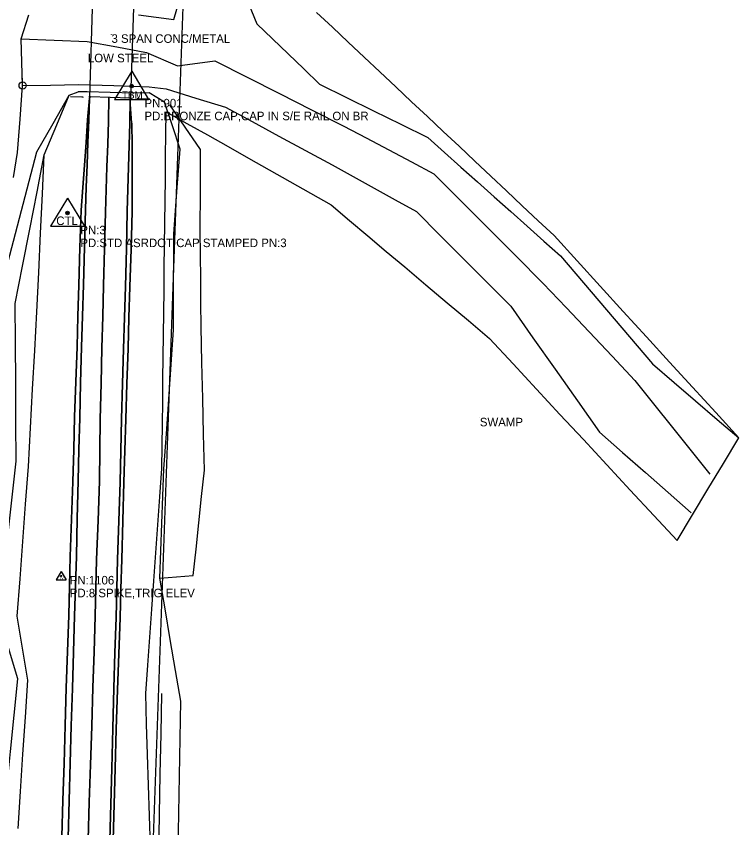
# Model space of a CAD drawing. Extents: x 1445297 to 1476720, y 2042269 to 2057889.
# Drawn here: x 1446040.2 to 1446463.1, y 2043652.1 to 2044126.9 of the extents above; entities that cross this region are included whole.
import ezdxf

# ---------------------------------------------------------------- set-up
doc = ezdxf.new("R2010")
doc.units = 0
for name, color, linetype in [('S_BRIDGE', 7, 'Continuous'), ('S_DITCHLINE', 7, 'Continuous'), ('S_EDGE_PAVEMENT', 7, 'Continuous'), ('S_MSC_PT_SYM', 7, 'Continuous'), ('S_PAVEMENT_CROWN', 7, 'Continuous'), ('S_PRIMARY_CTL', 7, 'Continuous'), ('S_PRIMARY_CTL_ANNOT', 7, 'Continuous'), ('S_SECONDARY_CTL', 7, 'Continuous'), ('S_SECONDARY_CTL_ANNOT', 7, 'Continuous'), ('S_SHOULDER', 7, 'Continuous'), ('S_STR_PT_SYM', 7, 'Continuous'), ('S_STREAM', 7, 'Continuous'), ('S_SURVEY_TEXT_ANNOT', 7, 'Continuous'), ('S_TREE', 7, 'Continuous'), ('S_UNDERGROUND_CABLE', 7, 'Continuous'), ('S_UTILITY_POLE', 7, 'Continuous'), ('S_WALL', 7, 'Continuous')]:
    doc.layers.add(name, color=color, linetype=linetype)

msp = doc.modelspace()

# ---------------------------------------------------------------- linework, layer by layer
at = {"layer": 'S_BRIDGE'}
for p, q in [((1446083.17, 2044079.68), (1446085.63, 2044154.69)), ((1446109.56, 2044154.24), (1446107.11, 2044078.9)), ((1446107.11, 2044078.9), (1446083.17, 2044079.68))]:
    msp.add_line(p, q, dxfattribs=at)
at = {"layer": 'S_DITCHLINE'}
for points in [[(1446111.81, 2044127.68), (1446132.33, 2044125.05), (1446137.31, 2044142.04)], [(1446174.36, 2044138.84), (1446180.96, 2044122.53), (1446190.14, 2044113.71), (1446199.32, 2044104.89), (1446208.5, 2044096.07), (1446217.68, 2044087.25), (1446233.53, 2044079.42), (1446249.37, 2044071.6), (1446265.21, 2044063.78), (1446281.05, 2044055.96), (1446290.76, 2044047.3), (1446300.47, 2044038.65), (1446310.17, 2044030), (1446319.88, 2044021.34), (1446329.59, 2044012.69), (1446339.29, 2044004.04), (1446349, 2043995.38), (1446358.71, 2043986.73), (1446372.18, 2043970.94), (1446385.64, 2043955.15), (1446399.11, 2043939.36), (1446412.57, 2043923.57), (1446425.2, 2043912.73), (1446437.84, 2043901.89), (1446450.47, 2043891.05), (1446463.1, 2043880.22)], [(1446038.65, 2044032.61), (1446041.01, 2044047.21), (1446042.47, 2044066.79), (1446043.93, 2044086.37), (1446043.53, 2044100.06), (1446043.13, 2044113.76), (1446047.64, 2044127.65)], [(1446043.13, 2044113.76), (1446062.46, 2044112.97), (1446081.78, 2044112.19), (1446099.08, 2044108.95), (1446116.39, 2044105.72), (1446134.56, 2044098), (1446156.52, 2044100.9), (1446175.36, 2044091.35), (1446194.2, 2044081.8), (1446213.05, 2044072.25), (1446231.89, 2044062.7), (1446245.08, 2044055.7), (1446258.27, 2044048.7), (1446271.47, 2044041.7), (1446284.66, 2044034.7), (1446300.63, 2044018.69), (1446316.61, 2044002.68), (1446332.59, 2043986.67), (1446348.57, 2043970.66), (1446362.01, 2043956.44), (1446375.45, 2043942.23), (1446388.9, 2043928.01), (1446402.34, 2043913.8), (1446413.28, 2043900.08), (1446424.21, 2043886.36), (1446435.14, 2043872.65), (1446446.08, 2043858.93)], [(1446043.93, 2044086.37), (1446060.25, 2044086.69), (1446076.57, 2044087.02), (1446097.32, 2044086.35), (1446118.08, 2044085.69), (1446127.94, 2044084.37), (1446145.34, 2044079.07), (1446162.74, 2044073.77), (1446178.33, 2044065.3), (1446193.92, 2044056.84), (1446209.51, 2044048.37), (1446225.1, 2044039.91), (1446237.42, 2044033.11), (1446249.74, 2044026.3), (1446262.05, 2044019.5), (1446274.37, 2044012.7), (1446288.18, 2043998.86), (1446302, 2043985.01), (1446315.81, 2043971.17), (1446329.62, 2043957.33), (1446342.63, 2043938.87), (1446355.64, 2043920.42), (1446368.65, 2043901.96), (1446381.66, 2043883.51), (1446395.05, 2043871.75), (1446408.44, 2043859.99), (1446421.82, 2043848.22), (1446435.21, 2043836.46)], [(1446041.28, 2043651.77), (1446042.71, 2043673.46), (1446044.14, 2043695.15), (1446045.57, 2043716.83), (1446047, 2043738.52), (1446043.87, 2043757.24), (1446040.73, 2043775.97), (1446042.39, 2043797.83), (1446044.04, 2043819.69), (1446045.69, 2043841.55), (1446047.35, 2043863.41), (1446048.57, 2043886.07), (1446049.79, 2043908.72), (1446051.01, 2043931.37), (1446052.23, 2043954.03), (1446053.33, 2043977), (1446054.42, 2043999.98), (1446055.51, 2044022.95), (1446056.6, 2044045.93), (1446063.91, 2044063.32), (1446071.21, 2044080.71)], [(1446134.89, 2043638.83), (1446135.28, 2043660.7), (1446135.66, 2043682.57), (1446136.05, 2043704.44), (1446136.44, 2043726.3), (1446133.38, 2043744.25), (1446130.32, 2043762.2), (1446127.26, 2043780.15), (1446124.2, 2043798.09), (1446143.79, 2043799.66), (1446145.41, 2043815.11), (1446147.04, 2043830.55), (1446148.67, 2043846), (1446150.3, 2043861.45), (1446149.83, 2043882.4), (1446149.36, 2043903.35), (1446148.89, 2043924.3), (1446148.42, 2043945.25), (1446148.29, 2043959.26), (1446148.16, 2043973.27), (1446148.02, 2043987.27), (1446147.89, 2044001.28), (1446147.95, 2044025.12), (1446148.02, 2044048.97), (1446139.09, 2044062.06), (1446130.17, 2044075.16)], [(1446134.89, 2043638.83), (1446135.28, 2043660.7), (1446135.66, 2043682.57), (1446136.05, 2043704.44), (1446136.44, 2043726.3), (1446133.38, 2043744.25), (1446130.32, 2043762.2), (1446127.26, 2043780.15), (1446124.2, 2043798.09), (1446143.79, 2043799.66), (1446145.41, 2043815.11), (1446147.04, 2043830.55), (1446148.67, 2043846), (1446150.3, 2043861.45), (1446149.83, 2043882.4), (1446149.36, 2043903.35), (1446148.89, 2043924.3), (1446148.42, 2043945.25), (1446148.29, 2043959.26), (1446148.16, 2043973.27), (1446148.02, 2043987.27), (1446147.89, 2044001.28), (1446147.95, 2044025.12), (1446148.02, 2044048.97), (1446139.09, 2044062.06), (1446130.17, 2044075.16)], [(1446033.44, 2043639.99), (1446032.52, 2043654.08), (1446034.68, 2043675.4), (1446036.84, 2043696.72), (1446039, 2043718.04), (1446041.15, 2043739.36), (1446035.65, 2043757.41), (1446030.16, 2043775.47), (1446032.65, 2043798.24), (1446035.14, 2043821.02), (1446037.63, 2043843.79), (1446040.13, 2043866.56), (1446040, 2043889.64), (1446039.87, 2043912.72), (1446039.74, 2043935.8), (1446039.61, 2043958.89), (1446043.86, 2043980.65), (1446048.11, 2044002.41), (1446052.36, 2044024.17), (1446056.6, 2044045.93)], [(1446123.61, 2043636.2), (1446124.06, 2043659.83), (1446124.51, 2043683.45), (1446124.96, 2043707.07), (1446125.41, 2043730.69)], [(1446123.61, 2043636.2), (1446124.06, 2043659.83), (1446124.51, 2043683.45), (1446124.96, 2043707.07), (1446125.41, 2043730.69)]]:
    msp.add_lwpolyline(points, dxfattribs=at)
at = {"layer": 'S_EDGE_PAVEMENT'}
for points in [[(1446070.63, 2043646.35), (1446071.19, 2043668.11), (1446071.75, 2043689.86), (1446072.38, 2043711.79), (1446073.02, 2043733.72), (1446073.67, 2043754.97), (1446074.32, 2043776.22), (1446074.84, 2043793.55), (1446075.37, 2043810.87), (1446075.87, 2043833.01), (1446076.37, 2043855.15), (1446076.85, 2043873.45), (1446077.33, 2043891.75), (1446077.87, 2043912.52), (1446078.42, 2043933.28), (1446078.96, 2043951.55), (1446079.5, 2043969.83), (1446080.07, 2043991.8), (1446080.64, 2044013.78), (1446081.15, 2044026.87), (1446081.66, 2044039.96), (1446082.17, 2044053.06), (1446082.67, 2044066.15), (1446083.03, 2044078.93)], [(1446083.03, 2044078.93), (1446082.67, 2044066.15), (1446082.17, 2044053.06), (1446081.66, 2044039.96), (1446081.15, 2044026.87), (1446080.64, 2044013.78), (1446080.07, 2043991.8), (1446079.5, 2043969.83), (1446078.96, 2043951.55), (1446078.42, 2043933.28), (1446077.87, 2043912.52), (1446077.33, 2043891.75), (1446076.85, 2043873.45), (1446076.37, 2043855.15), (1446075.87, 2043833.01), (1446075.37, 2043810.87), (1446074.84, 2043793.55), (1446074.32, 2043776.22), (1446073.67, 2043754.97), (1446073.02, 2043733.72), (1446072.38, 2043711.79), (1446071.75, 2043689.86), (1446071.19, 2043668.11), (1446070.63, 2043646.35)], [(1446094.96, 2043645.15), (1446095.51, 2043666), (1446096.05, 2043686.85), (1446096.66, 2043710.31), (1446097.26, 2043733.78), (1446097.93, 2043754.46), (1446098.6, 2043775.15), (1446099.05, 2043792.14), (1446099.51, 2043809.12), (1446100.27, 2043831.69), (1446101.03, 2043854.25), (1446101.4, 2043872.71), (1446101.77, 2043891.16), (1446102.4, 2043911.77), (1446103.03, 2043932.39), (1446103.56, 2043950.58), (1446104.09, 2043968.78), (1446104.64, 2043990.81), (1446105.18, 2044012.84), (1446105.54, 2044025.74), (1446105.9, 2044038.64), (1446106.26, 2044051.54), (1446106.62, 2044064.44), (1446106.88, 2044078.15)], [(1446106.88, 2044078.15), (1446106.62, 2044064.44), (1446106.26, 2044051.54), (1446105.9, 2044038.64), (1446105.54, 2044025.74), (1446105.18, 2044012.84), (1446104.64, 2043990.81), (1446104.09, 2043968.78), (1446103.56, 2043950.58), (1446103.03, 2043932.39), (1446102.4, 2043911.77), (1446101.77, 2043891.16), (1446101.4, 2043872.71), (1446101.03, 2043854.25), (1446100.27, 2043831.69), (1446099.51, 2043809.12), (1446099.05, 2043792.14), (1446098.6, 2043775.15), (1446097.93, 2043754.46), (1446097.26, 2043733.78), (1446096.66, 2043710.31), (1446096.05, 2043686.85), (1446095.51, 2043666), (1446094.96, 2043645.15)]]:
    msp.add_lwpolyline(points, dxfattribs=at)
at = {"layer": 'S_MSC_PT_SYM'}
for points in [[(1446095.94, 2044116.35), (1446095.94, 2044116.4), (1446095.94, 2044116.35), (1446095.89, 2044116.35), (1446095.94, 2044116.35), (1446095.94, 2044116.3), (1446095.94, 2044116.35), (1446095.99, 2044116.35)], [(1446082.12, 2044104.96), (1446082.12, 2044105.01), (1446082.12, 2044104.96), (1446082.07, 2044104.96), (1446082.12, 2044104.96), (1446082.12, 2044104.91), (1446082.12, 2044104.96), (1446082.17, 2044104.96)], [(1446311.54, 2043891.99), (1446311.54, 2043892.04), (1446311.54, 2043891.99), (1446311.49, 2043891.99), (1446311.54, 2043891.99), (1446311.54, 2043891.94), (1446311.54, 2043891.99), (1446311.59, 2043891.99)]]:
    msp.add_lwpolyline(points, dxfattribs=at)
at = {"layer": 'S_PAVEMENT_CROWN'}
for points in [[(1446082.19, 2043645.33), (1446082.94, 2043667.14), (1446083.69, 2043688.94), (1446084.34, 2043711.62), (1446085, 2043734.29), (1446085.7, 2043755.14), (1446086.4, 2043775.99), (1446086.75, 2043792.52), (1446087.1, 2043809.05), (1446088.05, 2043831.95), (1446089, 2043854.84), (1446089.19, 2043873.06), (1446089.37, 2043891.28), (1446089.85, 2043912.15), (1446090.34, 2043933.02), (1446090.81, 2043951.21), (1446091.29, 2043969.39), (1446091.87, 2043990.8), (1446092.45, 2044012.21), (1446092.87, 2044025.52), (1446093.3, 2044038.84), (1446093.73, 2044052.16), (1446094.15, 2044065.47), (1446094.45, 2044079.15)], [(1446094.45, 2044079.15), (1446094.15, 2044065.47), (1446093.73, 2044052.16), (1446093.3, 2044038.84), (1446092.87, 2044025.52), (1446092.45, 2044012.21), (1446091.87, 2043990.8), (1446091.29, 2043969.39), (1446090.81, 2043951.21), (1446090.34, 2043933.02), (1446089.85, 2043912.15), (1446089.37, 2043891.28), (1446089.19, 2043873.06), (1446089, 2043854.84), (1446088.05, 2043831.95), (1446087.1, 2043809.05), (1446086.75, 2043792.52), (1446086.4, 2043775.99), (1446085.7, 2043755.14), (1446085, 2043734.29), (1446084.34, 2043711.62), (1446083.69, 2043688.94), (1446082.94, 2043667.14), (1446082.19, 2043645.33)]]:
    msp.add_lwpolyline(points, dxfattribs=at)
at = {"layer": 'S_PRIMARY_CTL'}
for p, q in [((1446107.76, 2044094.78), (1446097.73, 2044078.26)), ((1446107.76, 2044094.78), (1446117.58, 2044078.26)), ((1446097.73, 2044078.26), (1446117.58, 2044078.26)), ((1446070.21, 2044020.54), (1446060.18, 2044004.03)), ((1446070.21, 2044020.54), (1446080.04, 2044004.03)), ((1446060.18, 2044004.03), (1446080.04, 2044004.03))]:
    msp.add_line(p, q, dxfattribs=at)
for centre, radius in [((1446107.76, 2044086.08), 1.04), ((1446107.76, 2044086.08), 0.609), ((1446107.76, 2044086.08), 0.344), ((1446070.21, 2044011.84), 1.04), ((1446070.21, 2044011.84), 0.609), ((1446070.21, 2044011.84), 0.344)]:
    msp.add_circle(centre, radius, dxfattribs=at)
at = {"layer": 'S_SECONDARY_CTL'}
for p, q in [((1446066.52, 2043802.1), (1446063.51, 2043797.15)), ((1446066.52, 2043802.1), (1446069.47, 2043797.15)), ((1446063.51, 2043797.15), (1446069.47, 2043797.15))]:
    msp.add_line(p, q, dxfattribs=at)
for radius in [0.311, 0.183, 0.103]:
    msp.add_circle((1446066.52, 2043799.49), radius, dxfattribs=at)
at = {"layer": 'S_SHOULDER'}
for points in [[(1446066.81, 2043646.76), (1446067.51, 2043668.29), (1446068.21, 2043689.83), (1446068.81, 2043711.97), (1446069.41, 2043734.11), (1446070.14, 2043755.26), (1446070.87, 2043776.41), (1446071.28, 2043793.66), (1446071.7, 2043810.92), (1446072.49, 2043832.73), (1446073.29, 2043854.54), (1446073.83, 2043873.52), (1446074.38, 2043892.49), (1446075.07, 2043912.97), (1446075.76, 2043933.45), (1446076.27, 2043951.55), (1446076.78, 2043969.64), (1446077.49, 2043991.59), (1446078.21, 2044013.54), (1446079.15, 2044026.71), (1446080.08, 2044039.88), (1446081.02, 2044053.06), (1446081.96, 2044066.23), (1446083.03, 2044078.93)], [(1446083.03, 2044078.93), (1446081.96, 2044066.23), (1446081.02, 2044053.06), (1446080.08, 2044039.88), (1446079.15, 2044026.71), (1446078.21, 2044013.54), (1446077.49, 2043991.59), (1446076.78, 2043969.64), (1446076.27, 2043951.55), (1446075.76, 2043933.45), (1446075.07, 2043912.97), (1446074.38, 2043892.49), (1446073.83, 2043873.52), (1446073.29, 2043854.54), (1446072.49, 2043832.73), (1446071.7, 2043810.92), (1446071.28, 2043793.66), (1446070.87, 2043776.41), (1446070.14, 2043755.26), (1446069.41, 2043734.11), (1446068.81, 2043711.97), (1446068.21, 2043689.83), (1446067.51, 2043668.29), (1446066.81, 2043646.76)], [(1446107.9, 2044064.39), (1446106.88, 2044078.15)], [(1446096.86, 2043645.15), (1446097.47, 2043665.98), (1446098.07, 2043686.8), (1446098.75, 2043709.82), (1446099.43, 2043732.83), (1446100.19, 2043753.92), (1446100.94, 2043775.01), (1446101.43, 2043792.02), (1446101.92, 2043809.04), (1446102.58, 2043831.72), (1446103.25, 2043854.41), (1446103.76, 2043872.79), (1446104.27, 2043891.16), (1446104.94, 2043911.83), (1446105.61, 2043932.49), (1446106.15, 2043950.6), (1446106.7, 2043968.71), (1446107.42, 2043990.74), (1446108.13, 2044012.78), (1446108.07, 2044025.68), (1446108.01, 2044038.59), (1446107.96, 2044051.49), (1446107.9, 2044064.39)], [(1446107.9, 2044064.39), (1446107.96, 2044051.49), (1446108.01, 2044038.59), (1446108.07, 2044025.68), (1446108.13, 2044012.78), (1446107.42, 2043990.74), (1446106.7, 2043968.71), (1446106.15, 2043950.6), (1446105.61, 2043932.49), (1446104.94, 2043911.83), (1446104.27, 2043891.16), (1446103.76, 2043872.79), (1446103.25, 2043854.41), (1446102.58, 2043831.72), (1446101.92, 2043809.04), (1446101.43, 2043792.02), (1446100.94, 2043775.01), (1446100.19, 2043753.92), (1446099.43, 2043732.83), (1446098.75, 2043709.82), (1446098.07, 2043686.8), (1446097.47, 2043665.98), (1446096.86, 2043645.15)]]:
    msp.add_lwpolyline(points, dxfattribs=at)
at = {"layer": 'S_STR_PT_SYM'}
for points in [[(1446083.17, 2044079.68), (1446083.17, 2044080.18), (1446083.17, 2044079.68), (1446082.67, 2044079.68), (1446083.17, 2044079.68), (1446083.17, 2044079.18), (1446083.17, 2044079.68), (1446083.67, 2044079.68)], [(1446107.11, 2044078.9), (1446107.11, 2044079.4), (1446107.11, 2044078.9), (1446106.61, 2044078.9), (1446107.11, 2044078.9), (1446107.11, 2044078.4), (1446107.11, 2044078.9), (1446107.61, 2044078.9)]]:
    msp.add_lwpolyline(points, dxfattribs=at)
at = {"layer": 'S_STREAM'}
for points in [[(1446035.35, 2043982.6), (1446040.97, 2044004.27), (1446046.58, 2044025.95), (1446052.2, 2044047.62), (1446061.71, 2044064.17), (1446071.21, 2044080.71), (1446076.37, 2044082.69)], [(1446124.2, 2043798.09), (1446124.82, 2043814.13), (1446125.43, 2043830.16), (1446126.04, 2043846.19), (1446126.65, 2043862.22), (1446128.06, 2043882.52), (1446129.47, 2043902.81), (1446130.88, 2043923.11), (1446132.29, 2043943.41), (1446132.31, 2043957.39), (1446132.32, 2043971.37), (1446132.33, 2043985.36), (1446132.35, 2043999.34), (1446134.27, 2044024.2), (1446136.19, 2044049.06), (1446131.56, 2044062.89), (1446126.93, 2044076.72), (1446117.96, 2044082.03), (1446108.71, 2044081.85), (1446095.19, 2044082.27), (1446081.67, 2044082.69), (1446076.37, 2044082.69)]]:
    msp.add_lwpolyline(points, dxfattribs=at)
at = {"layer": 'S_TREE'}
msp.add_lwpolyline([(1446118.71, 2043641.2), (1446118.16, 2043659.12), (1446117.61, 2043677.03), (1446117.07, 2043694.94), (1446116.52, 2043712.85), (1446115.98, 2043730.77), (1446117.16, 2043747.21), (1446118.35, 2043763.64), (1446119.53, 2043780.08), (1446120.71, 2043796.52), (1446121.9, 2043812.96), (1446123.08, 2043829.4), (1446124.27, 2043845.84), (1446125.45, 2043862.27), (1446125.61, 2043875.32), (1446125.76, 2043888.37), (1446125.92, 2043901.42), (1446126.07, 2043914.47), (1446126.23, 2043927.52), (1446126.39, 2043940.57), (1446126.54, 2043953.62), (1446126.7, 2043966.67), (1446126.85, 2043979.72), (1446127.01, 2043992.77), (1446127.16, 2044005.82), (1446127.32, 2044018.87), (1446127.47, 2044031.92), (1446127.63, 2044044.97), (1446127.78, 2044058.02), (1446127.94, 2044071.07), (1446140.01, 2044064.26), (1446152.08, 2044057.45), (1446164.15, 2044050.63), (1446176.22, 2044043.82), (1446188.29, 2044037.01), (1446200.36, 2044030.19), (1446212.42, 2044023.38), (1446224.49, 2044016.57), (1446235.26, 2044007.49), (1446246.03, 2043998.41), (1446256.8, 2043989.33), (1446267.57, 2043980.25), (1446279.99, 2043969.78), (1446292.41, 2043959.3), (1446304.84, 2043948.83), (1446317.26, 2043938.35), (1446330.98, 2043923.58), (1446344.71, 2043908.8), (1446358.43, 2043894.02), (1446372.15, 2043879.25), (1446385.88, 2043864.47), (1446399.6, 2043849.69), (1446413.32, 2043834.92), (1446427.05, 2043820.14), (1446436.06, 2043835.16), (1446445.07, 2043850.18), (1446454.09, 2043865.2), (1446463.1, 2043880.22), (1446449.58, 2043895.02), (1446436.06, 2043909.82), (1446422.54, 2043924.61), (1446409.02, 2043939.41), (1446395.51, 2043954.21), (1446381.99, 2043969.01), (1446368.47, 2043983.81), (1446354.95, 2043998.61), (1446345.68, 2044007.31), (1446336.41, 2044016.01), (1446327.15, 2044024.72), (1446317.88, 2044033.42), (1446308.61, 2044042.12), (1446299.34, 2044050.82), (1446290.08, 2044059.53), (1446280.81, 2044068.23), (1446271.54, 2044076.93), (1446262.27, 2044085.63), (1446253, 2044094.34), (1446243.74, 2044103.04), (1446234.47, 2044111.74), (1446225.2, 2044120.44), (1446215.93, 2044129.15)], dxfattribs=at)
at = {"layer": 'S_UNDERGROUND_CABLE'}
msp.add_line((1446141.2, 2044230.61), (1446119.29, 2043617.64), dxfattribs=at)
at = {"layer": 'S_UTILITY_POLE'}
msp.add_line((1446043.81, 2044088.51), (1446043.81, 2044090.62), dxfattribs=at)
msp.add_circle((1446043.93, 2044086.37), 2.13, dxfattribs=at)
at = {"layer": 'S_WALL'}
for points in [[(1446071.88, 2044079.96), (1446078.66, 2044079.74), (1446078.91, 2044079.75), (1446079.39, 2044079.5)], [(1446110.85, 2044078.91), (1446111.3, 2044078.76), (1446111.72, 2044078.77), (1446118.33, 2044078.66)]]:
    msp.add_lwpolyline(points, dxfattribs=at)

# ---------------------------------------------------------------- texts
at = {"layer": 'S_PRIMARY_CTL'}
for s, height, p in [('TBM', 4.287, (1446102.11, 2044078.69)), ('CTL', 5, (1446063.63, 2044004.76))]:
    msp.add_text(s, height=height, dxfattribs=at).set_placement(p)
at = {"layer": 'S_PRIMARY_CTL_ANNOT'}
for s, p in [('PN:901', (1446115.26, 2044073.58)), ('PD:BRONZE CAP,CAP IN S/E RAIL ON BR', (1446115.26, 2044066.08)), ('PN:3', (1446077.71, 2043999.34)), ('PD:STD ASRDOT CAP STAMPED PN:3', (1446077.71, 2043991.84))]:
    msp.add_text(s, height=5, dxfattribs=at).set_placement(p)
at = {"layer": 'S_SECONDARY_CTL'}
msp.add_text('TV', height=1.5, dxfattribs=at).set_placement((1446065.31, 2043797.48))
at = {"layer": 'S_SECONDARY_CTL_ANNOT'}
for s, p in [('PN:1106', (1446071.52, 2043794.49)), ('PD:8 SPIKE,TRIG ELEV', (1446071.52, 2043786.99))]:
    msp.add_text(s, height=5, dxfattribs=at).set_placement(p)
at = {"layer": 'S_SURVEY_TEXT_ANNOT'}
for s, p in [('3 SPAN CONC/METAL', (1446095.94, 2044111.35)), ('LOW STEEL', (1446082.12, 2044099.96)), ('SWAMP', (1446311.54, 2043886.99))]:
    msp.add_text(s, height=5, dxfattribs=at).set_placement(p)

doc.saveas('drawing.dxf')
